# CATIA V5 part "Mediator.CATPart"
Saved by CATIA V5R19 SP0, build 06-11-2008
Part number: Mediator
Material "Plastique": density 1200 kg/m3, Young's modulus 2.2e+09 Pa, Poisson ratio 0.38, thermal expansion 6.84e-05 1/K
Bounding box of the stored display mesh (mm): x -14.597 to 14.604, y 0 to 1, z -2.446 to 29.408
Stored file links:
  G:\project guitar elect\Mediator.CATPart
  C:\Program Files (x86)\Dassault Systemes\B19\intel_a\startup\materials\French\Catalog.CATMaterial
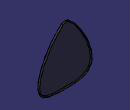
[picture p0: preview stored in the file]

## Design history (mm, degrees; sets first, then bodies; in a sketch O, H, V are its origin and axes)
Body1 (main body), material "Plastique"
  Sketch1 on zx-plane, origin (0, 0, 0), H (-1, 0, 0), V (0, 0, 1)
    point P1 (-12.5, 0.0247)
    point P2 (0, 30.0247)
    spline S1 through (0, 30.0247) (-7.3, 23) (-12.5, 0.0247) (0.0036, -2.52) (12.5, 0.0247) (7.3, 23) (0, 30.0247)
    arc A1 centre (0, 26.3274) radius 3.0804 from (1.8791, 28.7683) to (-1.8791, 28.7683) ccw
    point P3 (0, 26.3274)
    point P4 (1.8791, 28.7683)
    point P6 (-1.8791, 28.7683)
    point P7 (-1.8791, 28.7683)
    point P8 (0, 30.0247)
    point P10 (0, 30.0247)
    point P11 (-12.5, 0.0247)
    point P12 (7.3, 23)
    point P13 (-7.3, 23)
    distance P1 V = 12.5
    distance P2 V = 0
    distance P11 P1 = 0
    distance P12 V = 7.3
    distance V P13 = 7.3
    distance P12 H = 23
    distance H P13 = 23
    distance A1 S1 = 0
    coincidence: P8 P2, P10 P2, P3 V, A1 P4, P4 S1, A1 P6, S1 P7, P6 P7
  Pad1: profile Sketch1, direction (0, 1, 0), length 1
  Fillet1: radius 0.5, on end face of Pad1
  Fillet2: radius 0.5, on start face of Pad1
